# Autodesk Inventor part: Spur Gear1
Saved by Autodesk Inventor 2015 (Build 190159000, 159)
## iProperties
Created: 2014-06
Part Number: Spur Gear1
Material: Steel
Document SubType Name: Modeling
Designer: User
Categories: <?xml version="1.0" encoding="UTF-16"?> <MemberInstance><Categories><FamilyTemplate><FamilyTemplateParameter ValueType="xs:double" Id="1" ObjectReferenceKey="da
Density: 1 g/cm^3
Appearance: Steel
CustomPartVersion: 1
Author: User
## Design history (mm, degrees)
sketch "Sketch1"
  geometry: C1 r 10.888 at (0, 0)
  constraints: 1 centre point
  dimensions: "d0" = 21.77632 diameter of C1 (= da_da)
extrude "Extrusion1" new body sketch "Sketch1" distance "d1" = 2 (= da_b); taper "d2" = 0 deg
workplane "Work Plane2"
sketch "Sketch2"
  geometry: C1 r 10.888 at (0, 0) reference; C2 r 9.9 at (0, 0)
  constraints: 1 centre point, 1 coincident
  dimensions: "d3" = 19.8 diameter of C2 (= da_dw)
feature "Pitch Diameter" sketch "Sketch2" dims "d4" = 10, "d5" = 0
workplane "Work Plane8"
workplane "Work Plane9"
feature "Spur Gear" dims "da_b" = 2, "da_d" = 19.17791, "da_aw" = 19.8, "da_da" = 21.77632, "da_df" = 17.32368, "da_dw" = 19.8, angle "da_beta" = 55 deg, "da_lefttooth" = 10, "da_righttooth" = 0
body "Solid1"
body "Srf1"
other parameters: "d16" = 19.8 (= da_aw), "d17" = 0, "d34" = 2.85599 (computed from da_z), "d39" = 0, "d41" = 0, "d43" = 19.8 (= da_aw), "d46" = 19.8 (= da_aw), "d47" = 0, "d48" = 0
